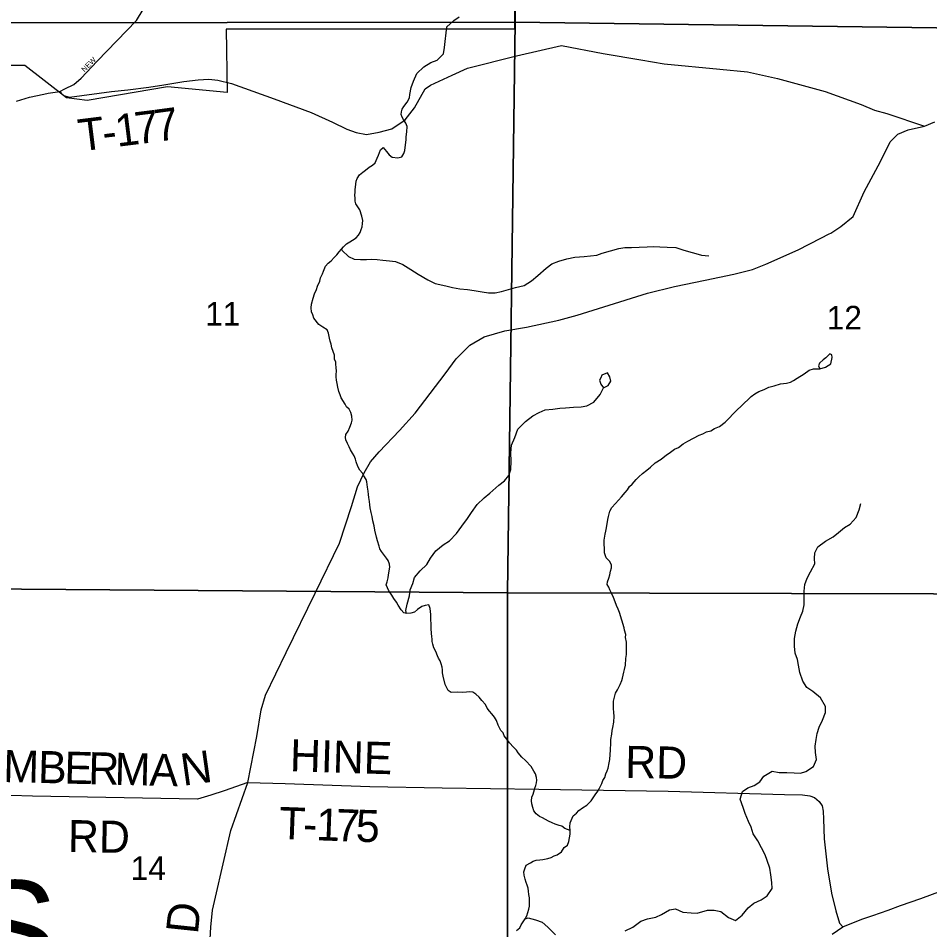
# Model space of a CAD drawing. Extents: x 1310247 to 1552180, y 377264 to 706493.
# Drawn here: x 1367792 to 1376326, y 499946 to 508475 of the extents above; entities that cross this region are included whole.
import ezdxf

# ---------------------------------------------------------------- set-up
doc = ezdxf.new("R2010")
doc.units = 0
for name, color, linetype in [('GM_X_City_Street', 7, 'Continuous'), ('GM_X_City_Street_Text', 7, 'Continuous'), ('GM_X_Corporation', 7, 'Continuous'), ('GM_X_County_Road', 7, 'Continuous'), ('GM_X_Minor_River', 7, 'Continuous'), ('GM_X_Section', 7, 'Continuous'), ('GM_X_Section_Text', 7, 'Continuous'), ('GM_X_State_Route', 7, 'Continuous'), ('GM_X_Township_Road', 7, 'Continuous'), ('GM_X_Township_Road_Text', 7, 'Continuous'), ('GM_X_Township_Text', 7, 'Continuous')]:
    doc.layers.add(name, color=color, linetype=linetype)

msp = doc.modelspace()

# ---------------------------------------------------------------- linework, layer by layer
at = {"layer": 'GM_X_City_Street'}
msp.add_lwpolyline([(1368229.7, 507813.1), (1368314, 507854.6), (1368380.3, 507915.4), (1368530.1, 508073.2), (1368900, 508454.4), (1369178, 508914), (1369613.8, 509610.7), (1369897.4, 510081.6), (1370117.6, 510516.1), (1370263.9, 510804.4), (1370335.4, 510914.4), (1370442.1, 511033.6), (1370707.6, 511278.7), (1371448.5, 511989), (1371989.8, 512499.6), (1372391.5, 512886.5), (1372660.4, 513144.1), (1372986.1, 513461.8), (1373324, 513763.4)], dxfattribs=at)
at = {"layer": 'GM_X_Corporation'}
msp.add_lwpolyline([(1372440.3, 512271), (1372439.9, 508371.4), (1369740, 508371.4), (1369749.8, 507780.2), (1369188.4, 507831.6), (1368437.3, 507704.2), (1368242.8, 507731.1), (1367853.8, 508033.9), (1367703.8, 508033.9)], dxfattribs=at)
at = {"layer": 'GM_X_County_Road'}
for points in [[(1368031.7, 507765.7), (1368072.8, 507774.7), (1368181.8, 507789.5), (1368229.7, 507813.1)], [(1367776.7, 507698.7), (1367898.1, 507736.2), (1368031.7, 507765.7)]]:
    msp.add_lwpolyline(points, dxfattribs=at)
at = {"layer": 'GM_X_Minor_River'}
for points in [[(1371455.4, 507729.6), (1371458, 507761.5), (1371470.1, 507827.2), (1371491.9, 507884.7), (1371524.3, 507957.9), (1371588.3, 508020), (1371653.7, 508062.1), (1371714.4, 508084.2), (1371772.2, 508140.6), (1371782.1, 508200.4), (1371806.2, 508394.1), (1371870.2, 508454.2), (1371921.3, 508488.7)], [(1370945.9, 506846.8), (1370946.6, 506870.9), (1370951.9, 506923), (1370956.7, 506951), (1370965.4, 506976.9), (1370986.4, 507008.5), (1371019.2, 507035.8), (1371043.8, 507053.2), (1371076.6, 507080.5), (1371109.3, 507099.8), (1371134, 507121.2), (1371153.2, 507166.9), (1371164, 507194.8), (1371174.7, 507218.6), (1371185.4, 507244.4), (1371210.1, 507265.9), (1371239.2, 507227), (1371264.6, 507198.2), (1371292.1, 507175.4), (1371346.1, 507168), (1371382.6, 507179.1), (1371403.4, 507208.7), (1371412.2, 507236.6), (1371415, 507266.6), (1371422.9, 507338.7), (1371425.6, 507364.8), (1371430.9, 507412.9), (1371432.3, 507463), (1371421, 507493.5), (1371397.8, 507526.2), (1371386.4, 507550.6), (1371377, 507574.9), (1371379.6, 507599), (1371388.3, 507624.9), (1371401.1, 507650.6), (1371432.2, 507690), (1371455.4, 507729.6)], [(1371171.6, 503534.7), (1371154.9, 503585.4), (1371147.8, 503619.7), (1371131.5, 503686.4), (1371124.5, 503726.8), (1371113.6, 503771.2), (1371106.7, 503813.6), (1371095.6, 503850), (1371086.7, 503894.5), (1371083.5, 503922.7), (1371080.3, 503952.9), (1371075.2, 503991.2), (1371071.9, 504017.4), (1371068.8, 504049.6), (1371063.7, 504085.9), (1371057, 504136.3), (1371049.6, 504160.6), (1371028.4, 504193.3), (1371015, 504219.7), (1370991.6, 504246.4), (1370972.4, 504281.1), (1370957.5, 504323.6), (1370950.2, 504349.9), (1370936.9, 504380.4), (1370921.5, 504406.9), (1370902.2, 504437.5), (1370891, 504466), (1370875.6, 504494.5), (1370860.5, 504529), (1370855.1, 504553.3), (1370859.9, 504581.3), (1370880.7, 504610.9), (1370897.8, 504648.6), (1370910.9, 504688.4), (1370917.6, 504714.4), (1370914.6, 504752.6), (1370905.5, 504787), (1370890.2, 504817.5), (1370864.6, 504838.2), (1370853.3, 504864.6), (1370814.7, 504923.9), (1370805.4, 504952.3), (1370794.2, 504982.7), (1370785.2, 505023.1), (1370778, 505057.4), (1370772.8, 505087.7), (1370769.7, 505119.9), (1370770.3, 505144), (1370770.9, 505168.1), (1370770, 505210.3), (1370766.7, 505234.5), (1370765.3, 505258.6), (1370753.9, 505283), (1370752.9, 505321.2), (1370741.8, 505357.6), (1370728.6, 505392.1), (1370721.5, 505426.5), (1370714.2, 505454.8), (1370706.9, 505481.1), (1370696.1, 505529.6), (1370684.9, 505560), (1370645.4, 505585.1), (1370607.8, 505608.2), (1370561.2, 505669.6), (1370550, 505700), (1370536.7, 505728.5), (1370535.7, 505766.7), (1370538.5, 505798.8), (1370552.1, 505856.7), (1370565.2, 505896.5), (1370584.4, 505938.2), (1370595.3, 505968), (1370614.6, 506015.8), (1370623.4, 506045.7), (1370640.5, 506083.4), (1370649.2, 506109.3), (1370668.5, 506155), (1370695.3, 506182.4), (1370722, 506203.8), (1370749, 506235.2), (1370775.7, 506260.7), (1370796.6, 506290.3), (1370817.3, 506313.8), (1370836, 506337.5), (1370864.8, 506362.8), (1370897.5, 506384.1), (1370922, 506397.5), (1370954.7, 506418.8), (1370977.4, 506444.3), (1370992.2, 506470), (1371003, 506497.9), (1371013.7, 506523.7), (1371016.6, 506555.8), (1371017.3, 506583.9), (1371010.3, 506622.2), (1370989.8, 506683), (1370953.1, 506738.2), (1370947.7, 506762.4), (1370946.5, 506792.6), (1370943.2, 506820.8), (1370945.9, 506846.8)], [(1370817.3, 506313.8), (1370824.5, 506301.5), (1370885.1, 506245.6), (1370936.7, 506222.1), (1370996.7, 506216.4), (1371052.9, 506216.9), (1371103.2, 506219.6), (1371153.3, 506218.2), (1371205.3, 506212.8), (1371267.3, 506205.1), (1371323.3, 506197.6), (1371392.8, 506171.6), (1371467.8, 506125.3), (1371536.8, 506081.3), (1371625.7, 506028.6), (1371697, 505992.6), (1371794.7, 505969.8), (1371858.5, 505956.1), (1371926.4, 505944.2), (1371998.5, 505938.2), (1372060.4, 505928.5), (1372134.3, 505916.5), (1372194.3, 505906.8), (1372256.5, 505907.1), (1372317, 505917.5), (1372381.8, 505937.9), (1372446.5, 505956.2), (1372529.3, 505974.1), (1372596.7, 506018.5), (1372656.2, 506067.1), (1372736.4, 506137.3), (1372787.7, 506178.1), (1372854.6, 506200.4), (1372927.4, 506222.5), (1373002.1, 506238.6), (1373090.6, 506244.2), (1373209.4, 506259.1), (1373260, 506275.8), (1373336.9, 506299.9), (1373415.8, 506321.9), (1373472.2, 506328.4), (1373532.5, 506330.8), (1373604.8, 506332.8), (1373681.1, 506336.8), (1373743.4, 506339.1), (1373799.5, 506335.6), (1373867.6, 506331.8), (1373949.8, 506329.5), (1374015.5, 506307.7), (1374067.2, 506292.2), (1374134.9, 506272.3), (1374190.7, 506258.7), (1374256.7, 506250.9)], [(1375297.2, 505194.1), (1375349.8, 505210.7), (1375398.9, 505241.6), (1375412.5, 505299.5), (1375409.2, 505325.7), (1375389.4, 505336.2), (1375352.2, 505297.1)], [(1375352.2, 505297.1), (1375327.7, 505279.6), (1375292.7, 505248.4), (1375286, 505222.5), (1375297.2, 505194.1)], [(1373256.7, 505136.7), (1373248, 505110.8), (1373235.3, 505087), (1373246.4, 505052.6), (1373271.5, 505015.7)], [(1373271.5, 505015.7), (1373314.2, 505038.7), (1373341.5, 505080.1), (1373332.5, 505118.5), (1373309.5, 505157.3), (1373256.7, 505136.7)], [(1373360.4, 501839.2), (1373369.7, 501887.2), (1373371.3, 501945.4), (1373368.2, 501979.6), (1373365.1, 502015.9), (1373366.9, 502084.1), (1373376.3, 502134.1), (1373385, 502160), (1373403.9, 502191.6), (1373429.3, 502241.2), (1373442.3, 502277), (1373449, 502301), (1373462.5, 502356.9), (1373469.2, 502380.8), (1373476.3, 502422.8), (1373482, 502484.9), (1373486.9, 502520.9), (1373487.6, 502545), (1373487.3, 502611.3), (1373488, 502637.4), (1373479.1, 502681.8), (1373479.8, 502707.9), (1373468.8, 502748.4), (1373465.5, 502772.6), (1373443.2, 502843.5), (1373423, 502914.3), (1373407.8, 502946.8), (1373394.6, 502979.3), (1373381.5, 503015.8), (1373366.5, 503054.3), (1373343.6, 503101.1), (1373330.2, 503125.6), (1373320.8, 503151.9), (1373305.4, 503176.4), (1373310.1, 503200.4), (1373321, 503234.3), (1373329.9, 503268.2), (1373338.8, 503300.1), (1373345.7, 503334.1), (1373346.4, 503358.2), (1373331.2, 503390.7), (1373295.9, 503425.8), (1373281.1, 503472.3), (1373280, 503506.5), (1373277.4, 503560.8), (1373278.3, 503592.9), (1373287.7, 503646.9), (1373292.5, 503674.9), (1373299.4, 503706.9), (1373311.5, 503784.9), (1373318.2, 503812.9), (1373331.6, 503862.7), (1373350.6, 503896.4), (1373383.8, 503935.7), (1373441.6, 503996.5), (1373474.8, 504037.8), (1373497.6, 504061.3), (1373514.5, 504095), (1373539.2, 504116.5), (1373576.4, 504157.7), (1373601.2, 504183.2), (1373636.2, 504216.5), (1373677.2, 504245.5), (1373712.1, 504274.8), (1373755.3, 504313.8), (1373810.5, 504348.6), (1373861.8, 504391.4), (1373886.3, 504406.9), (1373937.5, 504443.7), (1373974.1, 504458.8), (1374017.2, 504493.9), (1374062.1, 504518.8), (1374167.9, 504572.4), (1374200.4, 504585.6), (1374237.1, 504604.7), (1374275.5, 504615.8), (1374312.2, 504634.9), (1374356.9, 504655.9), (1374410.2, 504694.7), (1374449.3, 504731.8), (1374486.6, 504773), (1374527.8, 504814.2), (1374556.7, 504841.5), (1374589.7, 504874.8), (1374626.7, 504908), (1374653.6, 504935.5), (1374688.4, 504960.7), (1374727.1, 504981.8), (1374775.8, 505000.6), (1374818.6, 505021.6), (1374869.1, 505034.4), (1374929.9, 505052.9), (1374986.3, 505059.5), (1375022.7, 505070.6), (1375051.2, 505083.9), (1375084, 505107.2), (1375149.3, 505147.7), (1375196.4, 505182.6), (1375237, 505195.6), (1375297.2, 505194.1)], [(1371428.2, 502905.4), (1371420, 502931.9), (1371433.6, 502991.8), (1371453.9, 503071.6), (1371461.5, 503127.7), (1371485.1, 503185.3), (1371502.7, 503241.1), (1371554.6, 503304), (1371618.5, 503362.5), (1371652.2, 503421.9), (1371702.3, 503492.9), (1371772.1, 503549.3), (1371829.3, 503585.9), (1371895.4, 503652.4), (1371945.4, 503721.4), (1371997.6, 503794.3), (1372035.3, 503851.6), (1372089.5, 503924.5), (1372155.4, 503987), (1372206.8, 504029.8), (1372293.2, 504105.8), (1372344.4, 504146.6), (1372386, 504197.8), (1372405.6, 504253.5), (1372407.7, 504329.8), (1372403.8, 504408.2), (1372411.8, 504480.4), (1372441.9, 504551.9), (1372470.2, 504631.5), (1372540.4, 504701.9), (1372610, 504754.3), (1372669.1, 504786.8), (1372725.9, 504809.4), (1372796.4, 504817.6), (1372862.9, 504827.8), (1372917.2, 504830.4), (1372991.5, 504834.4), (1373061.9, 504838.5), (1373114.3, 504847.2), (1373181.5, 504883.5), (1373239.7, 504954.3), (1373271.5, 505015.7)], [(1375638.2, 503804.5), (1375664.3, 503876.1), (1375679.9, 503936)], [(1373474.6, 499936.8), (1373545.8, 499971), (1373621.6, 500027.2), (1373684.5, 500049.6), (1373761.1, 500063.6), (1373816, 500088.3), (1373889.4, 500132.5), (1373945.9, 500143), (1374013.3, 500111.1), (1374091.4, 500105), (1374147.5, 500101.4), (1374244.5, 500128.9), (1374308.8, 500129.2), (1374370.7, 500117.5), (1374441.3, 500059.3), (1374506.7, 500031.4), (1374570.4, 500084), (1374626.4, 500150.8), (1374677.8, 500195.6), (1374746.9, 500225.9), (1374804.2, 500264.5), (1374850.2, 500331.6), (1374847.7, 500387.9), (1374839.7, 500460.5), (1374829.3, 500521), (1374805.2, 500594), (1374784.6, 500646.8), (1374750.3, 500712), (1374717.9, 500777.2), (1374673.6, 500844.7), (1374653.3, 500905.6), (1374630.6, 500958.4), (1374598.6, 501033.6), (1374578.1, 501090.4), (1374550.1, 501169.5), (1374572.1, 501239.3), (1374623.3, 501274.1), (1374682.1, 501296.6), (1374735.2, 501331.3), (1374772.7, 501382.5), (1374850.3, 501428.7), (1374916.2, 501418.9), (1374988.5, 501418.9), (1375056.6, 501415.1), (1375114.7, 501411.5), (1375167.3, 501426.1), (1375236.8, 501474.5), (1375266.7, 501538), (1375256.5, 501604.6), (1375252.1, 501663), (1375263.9, 501726.9), (1375271.4, 501781), (1375291.1, 501840.7), (1375323.1, 501908.2), (1375351.1, 501979.8), (1375350.6, 502034), (1375304.7, 502117.6), (1375230.1, 502175.9), (1375176.9, 502213.5), (1375138.4, 502272.8), (1375110.6, 502354), (1375098.4, 502420.6), (1375087.8, 502475.1), (1375067.4, 502534), (1375059.1, 502598.5), (1375061.2, 502672.8), (1375071.1, 502740.8), (1375091, 502808.6), (1375116.9, 502874.2), (1375136.4, 502927.9), (1375150.1, 502987.8), (1375151.9, 503054.1), (1375149.6, 503114.4), (1375155.3, 503176.6), (1375177, 503236.2), (1375208.8, 503295.7), (1375251, 503370.9), (1375248.4, 503421.2), (1375249.8, 503473.4), (1375279.4, 503528.8), (1375351.1, 503581.2), (1375420.5, 503623.5), (1375471.7, 503662.3), (1375527.2, 503709), (1375580.3, 503741.7), (1375638.2, 503804.5)], [(1372959.2, 500873.3), (1372909.6, 500894.7), (1372882, 500915.5), (1372858, 500920.1), (1372820.3, 500935.2), (1372792.5, 500947.9), (1372756.7, 500962.9), (1372729, 500977.7), (1372701.3, 500994.5), (1372671.5, 501007.3), (1372642.1, 501032.2), (1372620.7, 501058.8), (1372609.4, 501089.2), (1372600.3, 501125.6), (1372599, 501151.8), (1372601.9, 501185.9), (1372612.7, 501213.7), (1372619.4, 501237.6), (1372630.3, 501271.5), (1372639, 501295.4), (1372645.6, 501319.3), (1372648.3, 501345.4), (1372643, 501371.6), (1372635.9, 501406), (1372620.5, 501430.5), (1372595.5, 501473.3), (1372540.7, 501528.9), (1372507.4, 501561.9), (1372472.3, 501601), (1372456.9, 501625.5), (1372429.5, 501654.3), (1372392.4, 501695.4), (1372365.3, 501730.3), (1372342, 501761), (1372332.6, 501787.4), (1372311.2, 501812), (1372286.4, 501860.9), (1372269.5, 501905.5), (1372252.1, 501934.1), (1372226.8, 501964.9), (1372205.4, 501991.5), (1372184.1, 502020.2), (1372166.9, 502054.8), (1372133.7, 502089.8), (1372106.5, 502122.6), (1372075.1, 502151.6), (1372049.4, 502168.3), (1372013.4, 502173.2), (1371989.2, 502169.8), (1371955, 502166.7), (1371908.8, 502167.9), (1371844.5, 502165.5), (1371818.9, 502186.3), (1371788.2, 502241.3), (1371770.2, 502318.1), (1371765, 502350.4), (1371763.7, 502378.5), (1371762.4, 502402.7), (1371753.1, 502433), (1371743.8, 502461.4), (1371728.4, 502485.9), (1371719, 502510.2), (1371702, 502550.9), (1371684.8, 502585.5), (1371673.6, 502617.9), (1371668.3, 502642.1), (1371666.9, 502666.3), (1371663.5, 502690.5), (1371662.2, 502716.6), (1371659.5, 502764.9), (1371658.7, 502813.1), (1371655.5, 502843.3), (1371656.2, 502867.4), (1371654.9, 502895.6), (1371648.3, 502952), (1371635.2, 502986.5), (1371600.9, 502979.3), (1371570.5, 502972.1), (1371529.6, 502943), (1371500.8, 502917.6), (1371466.4, 502908.5), (1371428.2, 502905.4), (1371402.2, 502912.1), (1371378.9, 502940.8), (1371347.8, 502981.8), (1371334.5, 503010.3), (1371307.3, 503045.1), (1371290, 503075.7), (1371263, 503116.6), (1371236.4, 503173.5), (1371245.2, 503201.4), (1371254.2, 503239.3), (1371259, 503267.3), (1371270.9, 503339.3), (1371269.7, 503367.5), (1371256.4, 503400), (1371239, 503424.5), (1371211.8, 503459.4), (1371194.4, 503485.9), (1371177, 503510.5), (1371171.6, 503534.7)], [(1372458.4, 499938.1), (1372489.3, 499965.5), (1372500, 499991.3), (1372520.8, 500018.9), (1372539.7, 500048.5), (1372554.5, 500076.3), (1372563.4, 500108.2), (1372574.2, 500138), (1372579, 500168), (1372580.3, 500218.2), (1372579, 500244.4), (1372573.8, 500274.6), (1372568.6, 500306.9), (1372567.4, 500335.1), (1372558.1, 500363.4), (1372546.7, 500389.8), (1372539.5, 500420.1), (1372528.4, 500456.6), (1372525.2, 500486.8), (1372534, 500516.7), (1372549, 500550.5), (1372587.7, 500573.6), (1372614.2, 500587), (1372642.6, 500598.3), (1372676.9, 500601.4), (1372703.1, 500604.7), (1372751.5, 500613.5), (1372781.8, 500620.8), (1372808.4, 500638.2), (1372838.8, 500647.5), (1372877.7, 500674.6), (1372904.9, 500716), (1372933.5, 500737.4), (1372946.6, 500773.2), (1372953.4, 500805.2), (1372958.3, 500839.2), (1372959.2, 500873.3), (1372956.1, 500907.6), (1372959.2, 500947.7), (1372989, 501011.2), (1373017.8, 501036.5), (1373040.6, 501062.1), (1373075.4, 501087.3), (1373116.2, 501112.3), (1373155.5, 501153.5), (1373174.3, 501181.2), (1373195.1, 501208.8), (1373220.1, 501244.2), (1373234.9, 501272), (1373256.2, 501315.6), (1373266.9, 501341.5), (1373283.8, 501371.2), (1373294.7, 501405), (1373305.5, 501432.9), (1373314.2, 501458.8), (1373323.5, 501506.7), (1373330.4, 501538.7), (1373336.8, 501628.9), (1373340.5, 501693.1), (1373339.3, 501725.3), (1373348.7, 501775.2), (1373353.6, 501809.3), (1373360.4, 501839.2)], [(1372539.7, 500048.5), (1372566.9, 500057.7), (1372636.6, 500039.8), (1372696.2, 500016.1), (1372751.1, 499970.4), (1372821.4, 499898.1)]]:
    msp.add_lwpolyline(points, dxfattribs=at)
at = {"layer": 'GM_X_Section'}
for points in [[(1367171.1, 513784.4), (1367295, 513781.4), (1372501.2, 513756.8), (1372445.8, 508439.6), (1367049.5, 508432.7)], [(1372603.2, 513756.4), (1377885.2, 513737.8), (1377881.8, 513677.9), (1377782.5, 508365.7), (1372445.8, 508439.6), (1372501.2, 513756.8)], [(1372445.8, 508439.6), (1372373.2, 503099.2), (1366992.5, 503140.2), (1367049.5, 508432.7)], [(1372445.8, 508439.6), (1377782.5, 508365.7), (1377691.2, 503085.5), (1372373.2, 503099.2)]]:
    msp.add_lwpolyline(points, close=True, dxfattribs=at)
for points in [[(1366992.5, 503140.2), (1372373.2, 503099.2), (1372373.3, 499782.9)], [(1372373.3, 499782.9), (1372373.2, 503099.2), (1377691.2, 503085.5), (1377663, 500105.9), (1377613.8, 500053), (1377544.2, 499984.6), (1377441.6, 499870.9)]]:
    msp.add_lwpolyline(points, dxfattribs=at)
at = {"layer": 'GM_X_State_Route'}
msp.add_lwpolyline([(1375414.1, 499903.8), (1375511.4, 499973.5), (1375690.1, 500044.2), (1375793.9, 500079.6), (1375935.4, 500129.1), (1376053.4, 500171.6), (1376242.1, 500240), (1376435.6, 500309.6)], dxfattribs=at)
at = {"layer": 'GM_X_Township_Road'}
for points in [[(1369789.1, 507864.2), (1370189, 507721.4), (1370536.3, 507592), (1370734.8, 507503.5), (1370869.9, 507436.6), (1370955, 507405.9), (1371051.4, 507387.8), (1371172.8, 507408.2), (1371289.7, 507438.8), (1371413.4, 507525.1), (1371501.9, 507637.4), (1371601.7, 507813.3), (1371652.8, 507849.6), (1371854.8, 507943.8), (1371997.7, 508008.5), (1372456.1, 508123.1), (1372877.1, 508220.7), (1373269.7, 508144.7), (1373620.3, 508085.6), (1373840.6, 508049.6), (1374361.3, 507997.1), (1374618.9, 507972.2), (1374901.4, 507909.7), (1375348.5, 507790.6), (1375685.5, 507669.2), (1375809.2, 507614.7), (1375923.8, 507584.1), (1376277.8, 507463.8)], [(1368181.8, 507789.5), (1368215.8, 507750.9), (1368271.4, 507737.3), (1368666.3, 507788.4), (1368818.3, 507806.5), (1369013.5, 507831.5), (1369156.5, 507851.9), (1369341.4, 507883.7), (1369477.6, 507898.4), (1369577.4, 507904.1), (1369661.4, 507896.1), (1369788.5, 507864.4), (1369789.1, 507864.2)], [(1375385.7, 506457.4), (1375400.9, 506465.1), (1375493.3, 506525.1), (1375610.2, 506620.9), (1375713.5, 506849.6), (1375865.9, 507133.6), (1375954.4, 507319.7), (1376025.9, 507388.9), (1376123.5, 507430.9), (1376277.8, 507463.8)], [(1376277.8, 507463.8), (1376375, 507504.3)], [(1369941.9, 501323.6), (1370024.9, 501754.1), (1370067.6, 502002.8), (1370108.7, 502142.3), (1370301.9, 502541.6), (1370573.8, 503094.3), (1370798.9, 503563.5), (1370911.3, 503905.7), (1370967.5, 504091.2), (1371030.4, 504220.3), (1371091.1, 504325.6), (1371170.9, 504418.8), (1371362.8, 504616.2), (1371510, 504778.2), (1371790.8, 505147.6), (1371892.7, 505287.5), (1372020.7, 505416.2), (1372154.1, 505492.9), (1372347.6, 505549), (1372549.8, 505582.9), (1372853.1, 505649.3), (1373024.5, 505695.8), (1373276.4, 505774), (1373683.1, 505902), (1373935.9, 505963.6), (1374222.6, 506025.2), (1374493.5, 506078.9), (1374666.4, 506123.9), (1374790.4, 506174.4), (1375093.7, 506307.1), (1375306.9, 506417.7), (1375385.7, 506457.4)], [(1369941.9, 501323.6), (1369720.9, 501246.9), (1369594, 501203.9), (1369471.2, 501169.1), (1367924.3, 501195.7), (1367517.1, 501208), (1367267.2, 501219.7), (1367165.1, 501228.5), (1367097.6, 501259.2), (1367026, 501320.6), (1366985.1, 501378.9), (1366970.7, 501439.2), (1366971.5, 501463.4)], [(1369227.3, 497471.4), (1369205.1, 497518.5), (1369209.1, 497595.9), (1369228.8, 497693.8), (1369472.9, 498497), (1369528.2, 498679.5), (1369543.2, 498792.4), (1369549.5, 498919.6), (1369574.8, 499477.9), (1369586.6, 499804.1), (1369595.8, 499970.6), (1369611.9, 500128.7), (1369637.9, 500250.3), (1369781.7, 500874.3), (1369941.9, 501323.6)], [(1369941.9, 501323.6), (1370292.8, 501313.4), (1371083.7, 501286.8), (1371761, 501272.5), (1372667.5, 501260.2), (1373877.8, 501241.8), (1374965.4, 501212.1), (1375134.2, 501207), (1375202.8, 501199.8), (1375246.8, 501183.4), (1375290.8, 501146.6), (1375319.4, 501104.7), (1375328.6, 501054.5), (1375330.6, 500981.9), (1375337.8, 500795.7), (1375368.1, 500517.2), (1375407, 500287.2), (1375446, 500124.4), (1375480, 500007.5), (1375511.4, 499973.5)]]:
    msp.add_lwpolyline(points, dxfattribs=at)

# ---------------------------------------------------------------- texts
at = {"layer": 'GM_X_City_Street_Text'}
msp.add_text('NEW', height=50, rotation=44.99762, dxfattribs=at).set_placement((1368412.2, 507967.5))
at = {"layer": 'GM_X_Section_Text'}
for s, p in [('11', (1369543, 505598.4)), ('12', (1375362, 505562.7)), ('14', (1368845.6, 500412.5))]:
    msp.add_text(s, height=221, rotation=0.00001, dxfattribs=at).set_placement(p)
at = {"layer": 'GM_X_Township_Road_Text'}
for s, rotation, p in [('7', 7.21057, (1368902.1, 507294.5)), ('7', 7.61869, (1369087.7, 507318)), ('T', 7.08927, (1368373.1, 507228.6)), ('1', 7.11758, (1368718.2, 507271.5)), ('-', 7.0974, (1368595.8, 507256.3)), ('HINE', 358.28438, (1370332.9, 501429.3)), ('RD', 359.00834, (1373472.9, 501367.8)), ('M', 358.60958, (1367649.6, 501328.3)), ('B', 358.60846, (1367975.1, 501320.4)), ('E', 358.60952, (1368221.4, 501314.4)), ('R', 358.60651, (1368445.7, 501309)), ('M', 358.60958, (1368692.1, 501303)), ('A', 358.69521, (1369018.1, 501295.1)), ('N', 7.96444, (1369334.8, 501292.1)), ('T', 357.891, (1370230.1, 500796.6)), ('1', 357.91377, (1370577.6, 500783.8)), ('7', 357.99597, (1370762.7, 500777)), ('5', 358.44519, (1370950, 500770.5)), ('RD', 359.01184, (1368256, 500673.7)), ('-', 357.89588, (1370454.3, 500788.3)), ('D', 83.99361, (1369473.3, 499898.8))]:
    msp.add_text(s, height=300, rotation=rotation, dxfattribs=at).set_placement(p)
at = {"layer": 'GM_X_Township_Text'}
msp.add_text('ROSS', height=900, rotation=0.00001, dxfattribs=at).set_placement((1364747.7, 499506.3))

doc.saveas('drawing.dxf')
